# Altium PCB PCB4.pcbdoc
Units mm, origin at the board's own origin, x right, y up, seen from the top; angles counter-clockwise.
Board outline 46.06 x 44.7 mm, 2 copper layers (Top Layer, Bottom Layer); 67 components, 65 nets, 250 pads, 138 vias.
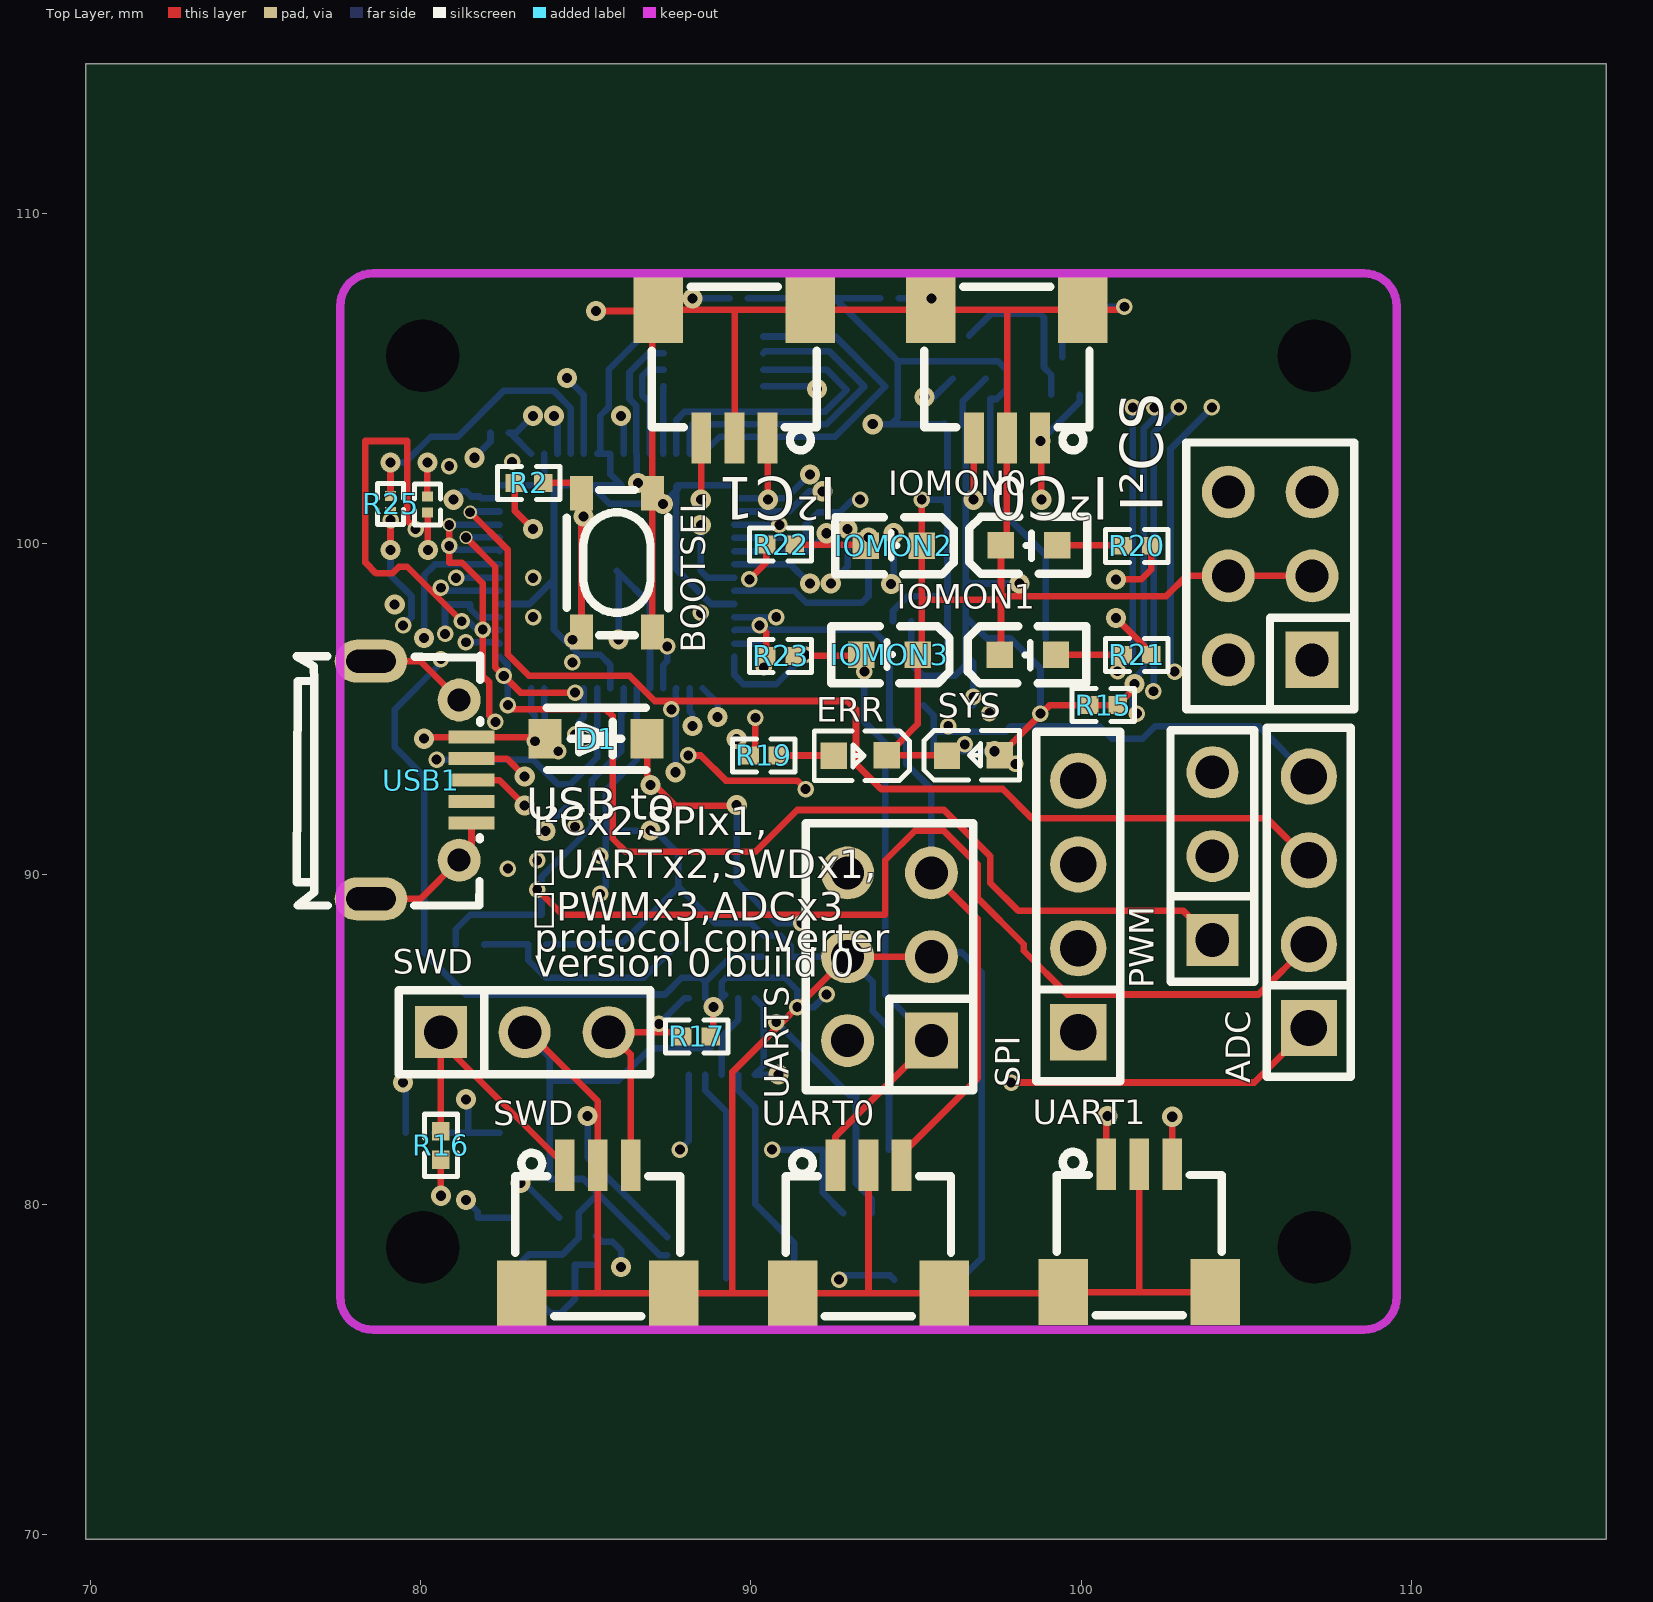
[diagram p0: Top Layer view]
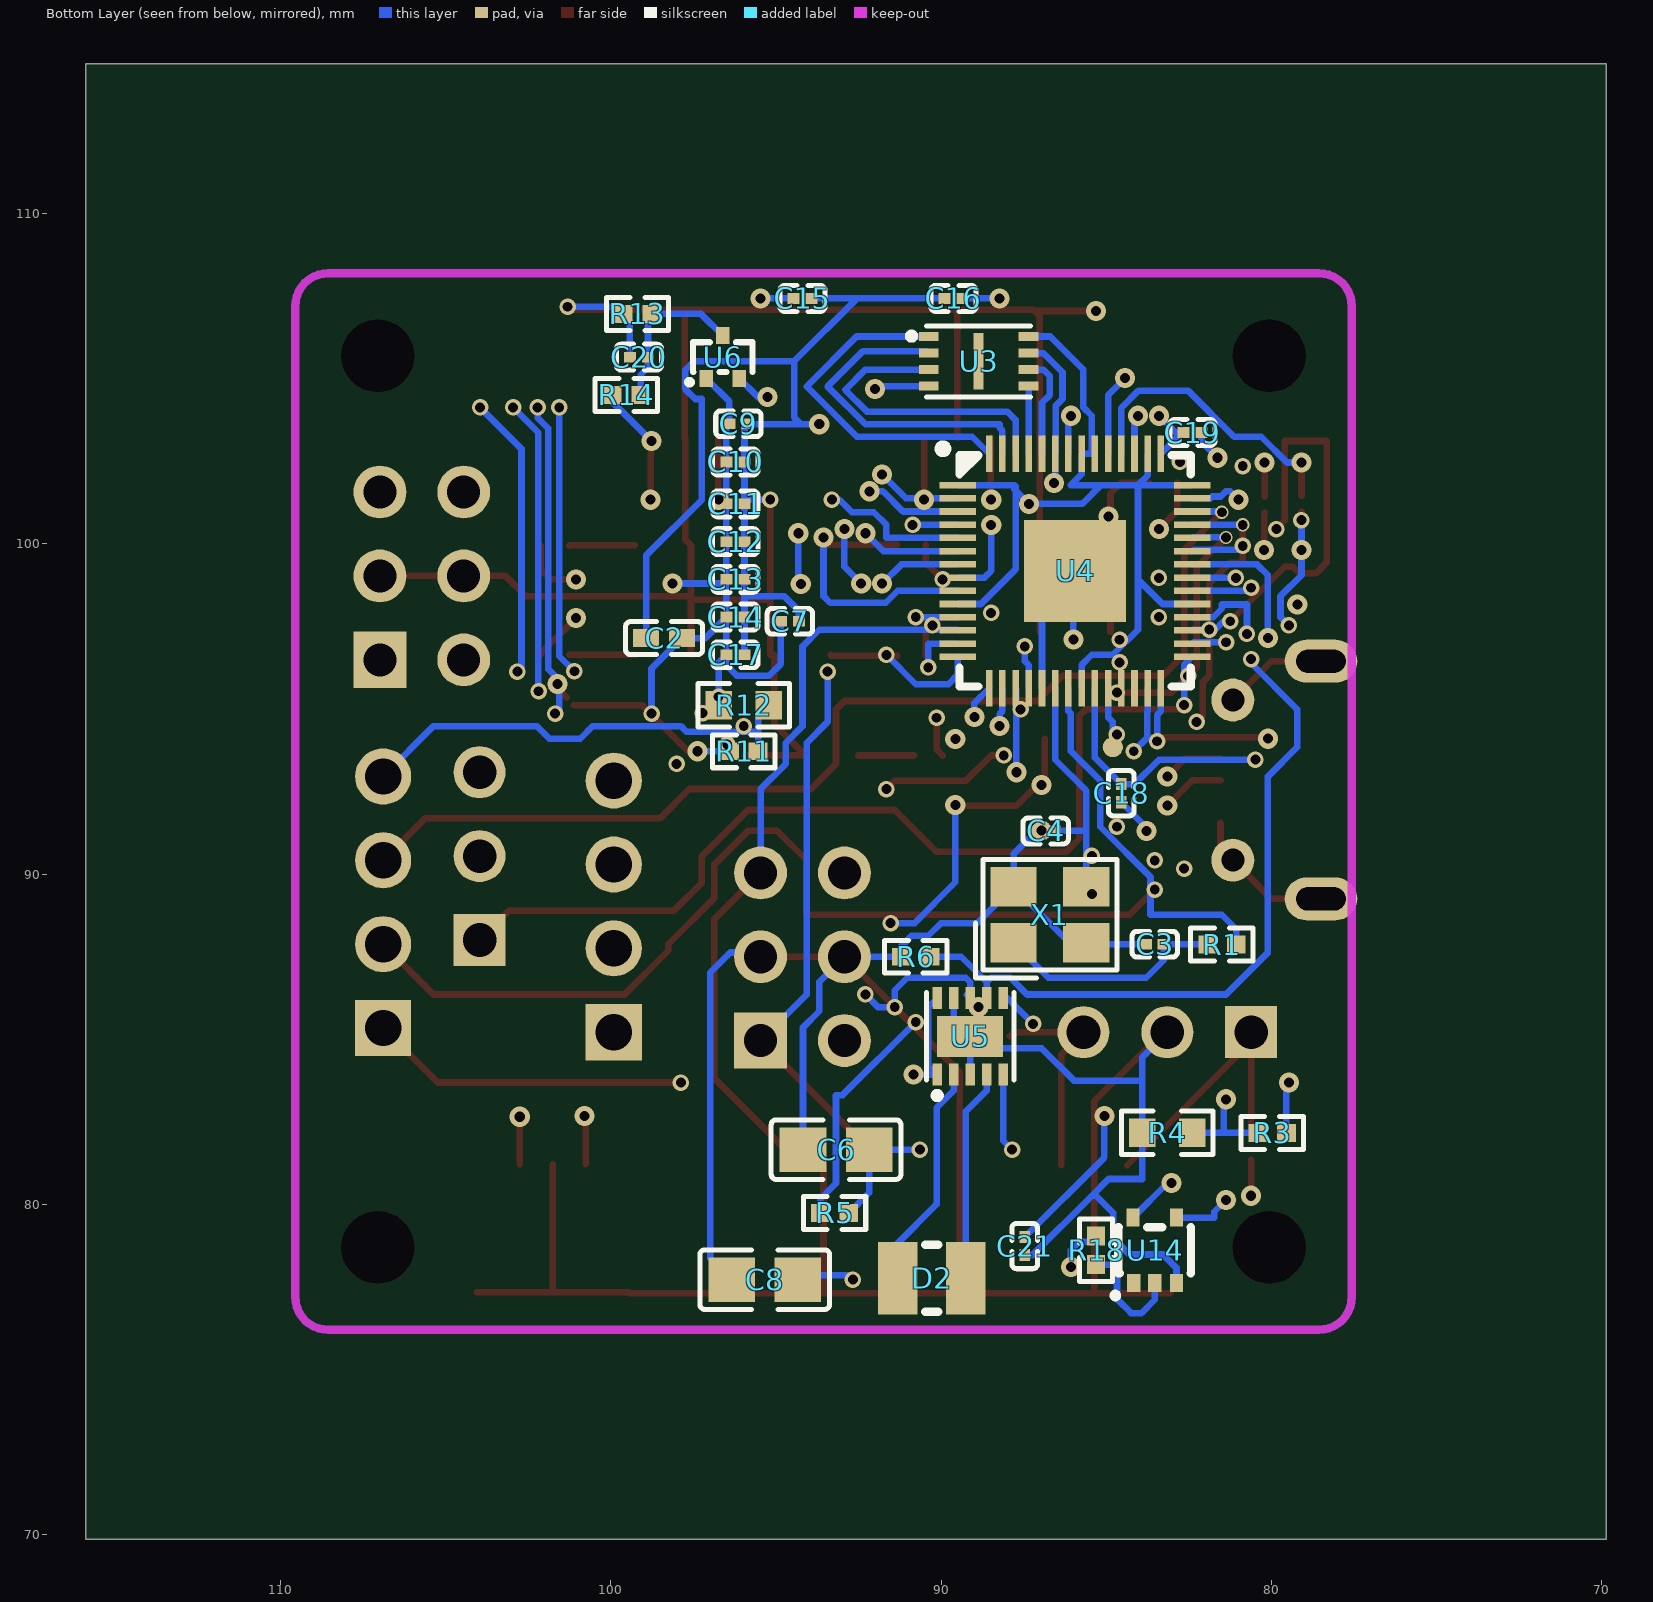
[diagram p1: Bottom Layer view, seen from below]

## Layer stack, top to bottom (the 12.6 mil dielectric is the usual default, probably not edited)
Top Layer: signal copper (thickness not stored)
Dielectric: dielectric 0.32, FR-4, Dk 4.8
Bottom Layer: signal copper (thickness not stored)

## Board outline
115.911,69.85 69.85,69.85 69.85,114.55 115.911,114.55
cut-out: 81.161,105.7 ccw(c80.061,105.7) 78.961,105.7 ccw(c80.061,105.7)
cut-out: 81.161,78.7 ccw(c80.061,78.7) 78.961,78.7 ccw(c80.061,78.7)
cut-out: 108.161,105.7 ccw(c107.061,105.7) 105.961,105.7 ccw(c107.061,105.7)
cut-out: 108.161,78.7 ccw(c107.061,78.7) 105.961,78.7 ccw(c107.061,78.7)

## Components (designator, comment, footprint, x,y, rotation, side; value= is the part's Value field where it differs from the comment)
ADC "2.54-1*4P母" HDR-TH_4P-P2.54-V-F 106.898,89.15 r90 top
BOOTSEL "SKRPACE010" KEY-SMD_4P-L4.2-W3.2-P2.20-LS4.6 85.943,99.437 r90 top
C2 "CL05A225MQ5NSNC" C0402 98.389,97.151 r0 bottom
C3 "CL03C150JA3ANNC" C0201 83.53,87.88 r180 bottom
C4 "CL03C150JA3ANNC" C0201 86.832,91.309 r180 bottom
C6 "GRM21BR60J476ME01L" C0805 93.182,81.657 r180 bottom
C7 "GRM033R60J104KE19D" C0201 94.579,97.659 r0 bottom
C8 "GRM21BR60J476ME01L" C0805 95.341,77.72 r0 bottom
C9 "GRM033R60J104KE19D" C0201 96.138,103.642 r180 bottom
C10 "GRM033R60J104KE19D" C0201 96.23,102.485 r180 bottom
C11 "GRM033R60J104KE19D" C0201 96.23,101.215 r180 bottom
C12 "GRM033R60J104KE19D" C0201 96.23,100.072 r180 bottom
C13 "GRM033R60J104KE19D" C0201 96.23,98.929 r180 bottom
C14 "GRM033R60J104KE19D" C0201 96.23,97.786 r180 bottom
C15 "GRM033R60J104KE19D" C0201 94.198,107.438 r0 bottom
C16 "GRM033R60J104KE19D" C0201 89.626,107.438 r0 bottom
C17 "GRM033R60J104KE19D" C0201 96.23,96.643 r0 bottom
C18 "GRM033R60J104KE19D" C0201 84.546,92.452 r90 bottom
C19 "GRM033R60J104KE19D" C0201 82.387,103.374 r0 bottom
C20 "GRM033R71E102KA01D" C0201 99.151,105.66 r180 bottom
C21 "GRM033R60J104KE19D" C0201 87.467,78.736 r270 bottom
D1 "MBR120VLSFT1G" SOD-123F_L2.8-W1.8-LS3.7-RD 85.308,94.103 r180 top
D2 "SRN2512-2R2M" IND-SMD_L2.5-W2.0 90.281,77.76 r180 bottom
ERR "NCD0603R1_C84263" LED0603-RD_RED 93.309,93.595 r180 top
IOMON0 "SZYY0603Y" LED0603-R-RD_YELLOW 98.425,99.96 r0 top
IOMON1 "SZYY0603Y" LED0603-R-RD_YELLOW 98.389,96.643 r0 top
IOMON2 "SZYY0603Y" LED0603-R-RD_YELLOW 94.325,99.945 r180 top
IOMON3 "SZYY0603Y" LED0603-R-RD_YELLOW 94.198,96.643 r180 top
I²C0 "SM03B-SRSS-TB(LF)(SN)" CONN-SMD_SM03B-SRSS-TB-LF-SN-P 97.754,105.152 r180 top
I²C1 "SM03B-SRSS-TB(LF)(SN)" CONN-SMD_SM03B-SRSS-TB-LF-SN-P 89.499,105.152 r180 top
I²CS "DS1023-2*3SF11" HDR-TH_6P-P2.54-V-F-R2-C3-S2.54 105.728,99.033 r90 top
PWM "2.54-1*3P母" HDR-TH_3P-P2.54-V-F 103.977,90.547 r90 top
R1 "AECR0402F1K00K9" R0402 81.496,87.868 r180 bottom
R2 "AECR0402F1K00K9" R0402 83.276,101.85 r0 top
R3 "CR0402F5K60Q10Z" R0402 79.974,82.165 r180 bottom
R4 "0603WAF1002T5E" R0603 83.149,82.165 r0 bottom
R5 "RC0402FR-07100KL" R0402 93.227,79.739 r180 bottom
R6 "RC0402FR-07100KL" R0402 90.769,87.499 r180 bottom
R11 "RC0402FR-071RL" R0402 95.976,93.722 r0 bottom
R12 "RC0603FR-07200RL" R0603 95.976,95.119 r180 bottom
R13 "RC0402FR-07100KL" R0402 99.196,106.968 r180 bottom
R14 "RC0402FR-07200KL" R0402 99.532,104.517 r0 bottom
R15 "RC0402FR-07470RL" R0402 100.675,95.119 r180 top
R16 "CR0402F100RQ10Z" R0402 80.609,81.784 r90 top
R17 "CR0402F100RQ10Z" R0402 88.356,85.086 r180 top
R18 "CR0402F100RQ10Z" R0402 85.308,78.609 r270 bottom
R19 "RC0402FR-07470RL" R0402 90.388,93.595 r0 top
R20 "RC0402FR-07470RL" R0402 101.691,99.945 r180 top
R21 "RC0402FR-07470RL" R0402 101.691,96.643 r180 top
R22 "RC0402FR-07470RL" R0402 90.897,99.982 r0 top
R23 "RC0402FR-07470RL" R0402 90.897,96.611 r0 top
R25 "RC0201FR-0727RL" R0201 79.085,101.215 r270 top
SPI "2.54-1*4P母" HDR-TH_4P-P2.54-V-F 99.913,89.023 r90 top
SWD "SM03B-SRSS-TB(LF)(SN)" CONN-SMD_SM03B-SRSS-TB-LF-SN-P 85.361,79.244 r0 top
SWD "2.54-1*3P母" HDR-TH_3P-P2.54-V-F 83.149,85.213 r0 top
SYS "19-217/GHC-YR1S2/3T" LED0603-RD 96.738,93.595 r0 top
U3 "W25Q16JVUXIQ" USON-8_L3.0-W2.0-P0.50-BL-EP 88.864,105.533 r270 bottom
U4 "RP2040_C2040" lqfn-56_l7.0-w7.0-p0.4-ep 85.943,99.183 r180 bottom
U5 "RT6150BGQW" WSON-10_L2.5-W2.5-P0.50-BL-EP 89.118,85.086 r180 bottom
U6 "DMG1012T-13" SOT-523-3_L1.6-W0.8-P1.00-LS1.6-BR 96.611,105.66 r270 bottom
U14 "74AUP1T17GWH" TSSOP-5_L2.1-W1.3-P0.65-LS2.2-BR 83.53,78.609 r270 bottom
UART0 "SM03B-SRSS-TB(LF)(SN)" CONN-SMD_SM03B-SRSS-TB-LF-SN-P 93.561,79.244 r0 top
UART1 "SM03B-SRSS-TB(LF)(SN)" CONN-SMD_SM03B-SRSS-TB-LF-SN-P 101.761,79.276 r0 top
UARTS "DS1023-2*3SF11" HDR-TH_6P-P2.54-V-F-R2-C3-S2.54 94.198,87.499 r90 top
USB1 "MicroXNJ" MICRO-USB-SMD_MICROXNJ 80.016,92.85 r270 top
X1 "X322512MMB4SI" CRYSTAL-SMD_4P-L3.2-W2.5-BL 86.705,88.769 r180 bottom
? "RC0201FR-0727RL" R0201 80.204,101.193 r270 top

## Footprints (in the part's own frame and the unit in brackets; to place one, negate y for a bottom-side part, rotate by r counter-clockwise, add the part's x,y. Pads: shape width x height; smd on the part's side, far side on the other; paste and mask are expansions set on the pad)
C0201 [mm]
  rect 0.368x0.324 smd paste-100 mask+0.051: 1(-0.274,0) 2(0.274,0)
  silkscreen extent -0.69,-0.39 0.69,0.39
C0402 [mm]
  rect 0.79x0.54 smd paste-100 mask+0.051: 1(-0.545,0) 2(0.545,0)
  silkscreen extent -1.17,-0.5 1.17,0.5
C0805 [mm]
  rect 1.41x1.35 smd paste-100 mask+0.051: 1(-1,0) 2(1,0)
  silkscreen extent -1.96,-0.9 1.96,0.9
CONN-SMD_SM03B-SRSS-TB-LF-SN-P [mm]
  rect 0.6x1.55 smd mask+0.051: 1(-1,1.938) 2(0,1.938) 3(1,1.938)
  rect 1.5x2 smd mask+0.051: 4(2.3,-1.938) 5(-2.3,-1.938)
  silkscreen extent -2.5,-2.64 2.5,2.32
CRYSTAL-SMD_4P-L3.2-W2.5-BL [mm]
  rect 1.4x1.2 smd paste+0 mask+0.051: 1(-1.1,-0.85) 2(1.1,-0.85) 3(1.1,0.85) 4(-1.1,0.85)
  silkscreen extent -2.26,-1.91 2.03,1.68
HDR-TH_3P-P2.54-V-F [mil]
  rect 62x62 hole 40.16 mask+2.01: 1(-100,0)
  round 62 hole 40.16 mask+2.01: 2(0,0) 3(100,0)
  silkscreen extent -150,-50 150,50
HDR-TH_4P-P2.54-V-F [mm]
  rect 1.7x1.7 hole 1.1 mask+0.051: 1(-3.81,0)
  round 1.7 hole 1.1 mask+0.051: 2(-1.27,0) 3(1.27,0) 4(3.81,0)
  silkscreen extent -5.29,-1.27 5.29,1.27
HDR-TH_6P-P2.54-V-F-R2-C3-S2.54 [mm]
  rect 1.7x1.6 hole 1 mask+0.051: 1(-2.54,-1.27)
  round 1.6 hole 1 mask+0.051: 2(-2.54,1.27) 3(0,-1.27) 4(0,1.27) 5(2.54,-1.27) 6(2.54,1.27)
  silkscreen extent -4.04,-2.54 4.04,2.54
IND-SMD_L2.5-W2.0 [mm]
  rect 1.2x2.2 smd paste+0 mask+0.051: 1(1.028,0) 2(-1.028,0)
  silkscreen extent -0.2,-1.02 0.2,1.02
KEY-SMD_4P-L4.2-W3.2-P2.20-LS4.6 [mm]
  rect 1.05x0.7 smd mask+0.051: 1(-2.1,1.075) 2(2.1,1.075) 3(-2.1,-1.075) 4(2.1,-1.075)
  silkscreen extent -2.2,-1.55 2.2,1.52
LED0603-R-RD_YELLOW [mm]
  rect 0.8x0.8 smd mask+0.051: 1(0.851,0) 2(-0.851,0)
  silkscreen extent -1.82,-0.86 1.77,0.86
LED0603-RD [mm]
  rect 0.8x0.8 smd paste+0 mask+0.051: 1(-0.799,-0.003) 2(0.799,0.003)
  silkscreen extent -1.49,-0.75 1.39,0.76
LED0603-RD_RED [mm]
  rect 0.8x0.8 smd mask+0.051: 1(-0.8,-0.003) 2(0.8,0.003)
  silkscreen extent -1.49,-0.75 1.39,0.76
lqfn-56_l7.0-w7.0-p0.4-ep [mm]
  rect 1.1x0.2 smd paste-100 mask+0.05: 1(-3.55,2.6) 2(-3.55,2.2) 3(-3.55,1.8) 4(-3.55,1.4) 5(-3.55,1) 6(-3.55,0.6) 7(-3.55,0.2) 8(-3.55,-0.2) 9(-3.55,-0.6) 10(-3.55,-1) 11(-3.55,-1.4) 12(-3.55,-1.8) 13(-3.55,-2.2) 14(-3.55,-2.6) 29(3.55,-2.6) 30(3.55,-2.2) 31(3.55,-1.8) 32(3.55,-1.4) 33(3.55,-1) 34(3.55,-0.6) 35(3.55,-0.2) 36(3.55,0.2) 37(3.55,0.6) 38(3.55,1) 39(3.55,1.4) 40(3.55,1.8) 41(3.55,2.2) 42(3.55,2.6)
  rect 0.2x1.1 smd paste-100 mask+0.05: 15(-2.6,-3.55) 16(-2.2,-3.55) 17(-1.8,-3.55) 18(-1.4,-3.55) 19(-1,-3.55) 20(-0.6,-3.55) 21(-0.2,-3.55) 22(0.2,-3.55) 23(0.6,-3.55) 24(1,-3.55) 25(1.4,-3.55) 26(1.8,-3.55) 27(2.2,-3.55) 28(2.6,-3.55) 43(2.6,3.55) 44(2.2,3.55) 45(1.8,3.55) 46(1.4,3.55) 47(1,3.55) 48(0.6,3.55) 49(0.2,3.55) 50(-0.2,3.55) 51(-0.6,3.55) 52(-1,3.55) 53(-1.4,3.55) 54(-1.8,3.55) 55(-2.2,3.55) 56(-2.6,3.55)
  rect 3.1x3.1 smd paste-100 mask+0.05: 57(0,0)
  silkscreen extent -4.13,-3.5 3.5,3.83
MICRO-USB-SMD_MICROXNJ [mm]
  rect 0.4x1.4 smd paste-100 mask+0.051: 1(-1.3,1.521) 2(-0.65,1.521) 3(0,1.521) 4(0.65,1.521) 5(1.3,1.521)
  round 1.3 hole 0.7 mask+0.051: 6(2.425,1.149) 9(-2.425,1.149)
  oval 1.3x2.2 hole 0.7 slot 1.5 at 90 deg mask+0.051: 7(3.6,-1.521) 8(-3.6,-1.521)
  silkscreen extent -3.76,-3.78 3.8,1.79
R0201 [mm]
  rect 0.303x0.324 smd paste-100 mask+0.051: 1(-0.242,0) 2(0.242,0)
  silkscreen extent -0.62,-0.39 0.62,0.39
R0402 [mm]
  rect 0.566x0.54 smd paste-100 mask+0.051: 1(-0.433,0) 2(0.433,0)
  silkscreen extent -0.94,-0.5 0.94,0.5
R0603 [mm]
  rect 0.806x0.864 smd paste-100 mask+0.051: 1(-0.753,0) 2(0.753,0)
  silkscreen extent -1.39,-0.66 1.39,0.66
SOD-123F_L2.8-W1.8-LS3.7-RD [mm]
  rect 1x1.2 smd paste+0 mask+0.051: 1(-1.55,0) 2(1.55,0)
  silkscreen extent -1.52,-0.93 1.49,0.95
SOT-523-3_L1.6-W0.8-P1.00-LS1.6-BR [mm]
  rect 0.51x0.4 smd paste+0 mask+0.051: 1(0.65,-0.5) 2(0.65,0.5) 3(-0.65,0)
  silkscreen extent -0.45,-1.08 0.83,0.9
TSSOP-5_L2.1-W1.3-P0.65-LS2.2-BR [mil]
  rect 21.7x15.7 smd paste+0 mask+1.97: 1(39,-25) 2(39,0) 3(39,26) 4(-39,26) 5(-39,-26)
  silkscreen extent -28,-49 56,43
USON-8_L3.0-W2.0-P0.50-BL-EP [mm]
  rect 0.28x0.6 smd paste+0 mask+0.051: 1(-0.75,-1.507) 2(-0.25,-1.507) 3(0.25,-1.507) 4(0.75,-1.507) 5(0.75,1.507) 6(0.25,1.507) 7(-0.25,1.507) 8(-0.75,1.507)
  rect 1.7x0.3 smd paste+0 mask+0.051: 9(0,0)
  silkscreen extent -1.08,-2.13 1.08,1.58
WSON-10_L2.5-W2.5-P0.50-BL-EP [mm]
  rect 0.28x0.665 smd paste+0 mask+0.051: 1(-1,-1.157) 2(-0.5,-1.157) 3(0,-1.157) 4(0.5,-1.157) 5(1,-1.157) 6(1,1.157) 7(0.5,1.157) 8(0,1.157) 9(-0.5,1.157) 10(-1,1.157)
  rect 2x1.25 smd paste+0 mask+0.051: 11(0,0)
  silkscreen extent -1.33,-1.89 1.33,1.33

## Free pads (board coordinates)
  round 0.61 smd far side mask+0.051: TP1(84.8,93.849)

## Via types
v1: diameter 0.5, hole 0.3, Top Layer to Bottom Layer, 68 vias
v2: diameter 0.61, hole 0.305, Top Layer to Bottom Layer, 65 vias
v3: diameter 0.4, hole 0.3, Top Layer to Bottom Layer, 3 vias
v4: diameter 0.5, hole 0.305, Top Layer to Bottom Layer, 2 vias

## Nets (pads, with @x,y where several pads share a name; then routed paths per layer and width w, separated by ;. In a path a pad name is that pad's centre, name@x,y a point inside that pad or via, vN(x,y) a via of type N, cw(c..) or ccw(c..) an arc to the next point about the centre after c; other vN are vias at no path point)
0ADC0: ADC.1 U4.38 | length 41.9
  Top Layer w0.2: v3(81.371,100.199) 82.26,99.31 82.26,96.262 83.022,95.5 v1(84.673,95.5) ; v1(97.881,83.689) 105.247,83.689 ADC.1
  Inner1 w0.2: v1(84.673,91.436) v1(84.673,94.23) ; v1(85.435,89.404) v1(85.435,90.551)
  Inner2 w0.2: v1(84.673,91.436) 84.673,91.313 v1(85.435,90.551) ; v1(84.673,94.23) v1(84.673,95.5) ; v1(85.435,89.404) 91.531,89.404 92.293,88.642 94.198,88.642 94.198,83.689 v1(97.881,83.689)
  Bottom Layer w0.2: v3(81.371,100.199) 82.377,100.199 U4.38
0ADC1: ADC.2 U4.39 | length 43.8
  Top Layer w0.2: v3(80.863,100.58) 80.863,99.437 81.244,99.437 81.879,98.802 81.879,96.008 82.079,95.808 82.079,94.792 v1(82.26,94.611) ; v1(83.53,89.531) 84.292,88.769 94.071,88.769 94.071,90.42 94.96,91.309 95.849,91.309 96.865,90.293 96.865,89.277 98.262,87.88 98.262,87.68 99.586,86.356 105.374,86.356 ADC.2
  Inner1 w0.2: v1(82.26,94.611) 82.105,94.455 82.105,89.814 82.387,89.531 v1(83.53,89.531)
  Bottom Layer w0.2: v3(80.863,100.58) 82.39,100.58 U4.39
0ADC2: ADC.3 U4.40 | length 33.5
  Top Layer w0.2: v3(81.498,100.961) 82.641,99.818 82.641,96.643 83.276,96.008 86.324,96.008 87.086,95.246 92.928,95.246 93.182,94.992 93.182,93.341 93.944,92.579 97.627,92.579 98.516,91.69 105.628,91.69 ADC.3
  Bottom Layer w0.2: v3(81.498,100.961) 81.52,100.983 U4.40
0CPU-U: R15.1 U4.37 | length 32.9
  Top Layer w0.2: v1(88.102,93.595) 88.483,93.595 89.245,92.833 91.404,92.833 v1(91.658,92.579) ; R15.1@101.333,95.344 101.619,95.63 v2(101.619,95.754)
  Inner1 w0.2: v1(80.863,99.945) 80.863,99.691 84.165,96.389 84.165,95.26 84.433,94.992 v1(87.594,94.992) ; v1(96.476,93.93) 97.221,94.675 v1(97.221,94.88)
  Inner2 w0.2: v1(87.594,94.992) 87.594,94.103 v1(88.102,93.595) ; v1(91.658,92.579) 91.658,94.611 92.166,95.119 94.706,95.119 95.468,94.357 95.468,94.087 95.707,93.849 96.395,93.849 v1(96.476,93.93) ; v1(97.221,94.88) 97.642,94.88 99.786,97.024 101.564,97.024 101.691,96.897 101.691,95.826 v2(101.619,95.754)
  Bottom Layer w0.2: v1(80.863,99.945) 80.977,99.831 82.345,99.831 U4.37
0GP10: R19.1 U4.13 | length 4.5
  Top Layer w0.2: R19.1 90.134,93.774 v1(90.134,94.738)
  Inner1 w0.2: v1(90.134,94.738) 90.388,94.992 v1(90.388,96.262)
  Bottom Layer w0.2: U4.13 90.388,96.983 v1(90.388,96.262)
0GP11: R20.1 U4.14 | length 22.8
  Top Layer w0.2: v2(101.056,98.929) 101.823,98.929 102.124,99.23 R20.1
  Inner1 w0.2: v1(88.483,97.913) 88.61,98.04 89.245,98.04 89.245,99.056 89.626,99.437 100.548,99.437 v2(101.056,98.929)
  Inner2 w0.2: v1(88.483,97.913) 89.753,96.643 v1(91.658,96.643)
  Bottom Layer w0.2: U4.14 89.499,96.577 89.499,96.031 89.777,95.754 90.769,95.754 v1(91.658,96.643)
0GP15: R21.1 U4.18 | length 18.9
  Top Layer w0.2: v2(101.056,97.762) 102.124,96.695 R21.1
  Inner1 w0.2: v1(95.976,94.484) 96.738,95.246 v1(96.738,95.373)
  Inner2 w0.2: v1(87.467,96.897) 88.437,96.897 89.882,95.452 95.008,95.452 v1(95.976,94.484) ; v1(96.738,95.373) 99.024,97.659 100.953,97.659 v2(101.056,97.762)
  Bottom Layer w0.2: U4.18 87.343,96.333 87.467,96.457 v1(87.467,96.897)
0GP19: R22.1 U4.30 | length 12.5
  Top Layer w0.2: v1(89.953,98.925) 90.464,99.436 R22.1
  Inner1 w0.2: v1(84.593,97.098) 84.774,97.098 85.308,96.564 88.277,96.564 89.953,98.239 v1(89.953,98.925)
  Inner2 w0.2: v1(81.371,97.024) 84.519,97.024 v1(84.593,97.098)
  Bottom Layer w0.2: v1(81.371,97.024) 82.352,97.024 U4.30
0GP21: R23.1 U4.32 | length 14.4
  Top Layer w0.2: v1(90.261,97.532) 90.464,97.329 R23.1
  Inner1 w0.2: v1(84.593,96.414) 84.745,96.262 88.991,96.262 v1(90.261,97.532)
  Inner2 w0.2: v1(80.736,97.278) 80.736,97.049 81.161,96.624 84.383,96.624 v1(84.593,96.414)
  Bottom Layer w0.2: v1(80.736,97.278) 80.736,98.167 81.498,98.167 81.498,98.04 81.755,97.783 U4.32
0GPIO23: R6.2 U4.35 U5.7 | length 32.1
  Inner1 w0.2: v1(81.879,97.405) 82.514,96.77 v4(82.514,96.008) ; v1(83.403,97.786) v1(83.403,98.972)
  Inner2 w0.2: v1(80.609,96.516) 80.609,96.262 82.26,96.262 v4(82.514,96.008) ; v1(81.075,98.972) v1(83.403,98.972) ; v1(81.879,97.405) 83.022,97.405 v1(83.403,97.786)
  Bottom Layer w0.2: v1(80.609,96.516) 80.609,96.389 79.212,94.992 79.212,93.849 80.101,92.96 80.101,87.626 81.371,86.356 87.394,86.356 87.902,86.864 88.481,86.864 88.618,86.727 ; v1(81.075,98.972) 82.382,98.972 U4.35 ; U5.7 88.618,86.727 ; R6.2 89.39,87.499 88.618,86.727
0GPIO24: R3.1 R4.1 U4.36 | length 22.6
  Inner2 w0.2: v2(80.101,97.151) 80.101,94.992 82.26,92.833 82.26,89.277 81.776,88.793 81.776,83.586 v2(81.371,83.181)
  Bottom Layer w0.2: v2(80.101,97.151) 80.101,99.056 80.428,99.383 U4.36 ; R3.1 81.434,82.165 ; v2(81.371,83.181) 81.434,83.118 81.434,82.165 ; R4.1 81.434,82.165
0USB0: ?.1 U4.47 | length 8.8
  Top Layer w0.2: ?.1 80.204,102.461 v2(80.21,102.468)
  Inner2 w0.2: v2(80.21,102.468) 82.768,105.025 v2(84.425,105.025)
  Bottom Layer w0.2: v2(84.425,105.025) 84.943,104.507 U4.47
0USB1: R25.1 U4.46 | length 9
  Top Layer w0.2: R25.1 v2(79.085,102.468)
  Bottom Layer w0.2: v2(79.085,102.468) 79.526,102.468 80.305,103.247 81.125,103.247 82.522,104.644 84.019,104.644 84.546,104.117 84.546,102.736 U4.46
1V10: C15.2 C16.1 C18.2 U4.23 U4.45 U4.50 | length 45.6
  Inner1 w0.2: v1(79.085,100.723) 79.229,100.723 v1(80.863,102.358) ; v1(79.466,97.532) 80.101,96.897 80.101,94.865 80.863,94.103 80.863,93.849 v1(80.482,93.468)
  Inner2 w0.2: v1(80.863,102.358) 80.863,102.612 81.371,103.12 81.498,103.12 81.752,103.374 82.133,103.374 82.768,104.009 82.768,104.39 84.165,104.39 84.673,103.882 ; v2(84.038,103.882) 84.673,103.882 ; v2(86.07,103.882) 86.07,104.136 88.275,106.341 ; v2(88.229,107.438) 87.704,106.913 ; v2(95.468,107.438) 89.372,107.438 88.275,106.341 ; 84.673,103.882 87.704,106.913 ; 87.704,106.913 88.275,106.341
  Bottom Layer w0.2: v1(79.085,100.723) 79.085,99.056 79.72,98.421 79.72,97.786 v1(79.466,97.532) ; v1(80.482,93.468) 83.403,93.468 84.145,92.726 C18.2 85.343,93.523 U4.23 ; v2(84.038,103.882) 84.143,103.777 U4.45 ; v2(86.07,103.882) 86.143,103.809 U4.50 ; v2(88.229,107.438) C16.1 ; C15.2 v2(95.468,107.438)
12: R16.1 U4.15 | length 21.3
  Top Layer w0.2: v2(80.609,80.26) R16.1
  Inner1 w0.2: v2(80.609,80.26) 84.292,83.943 84.292,90.293 85.943,91.944 87.975,91.944 88.61,92.579 88.61,94.23 88.704,94.324 88.704,94.471 v2(88.991,94.758)
  Bottom Layer w0.2: U4.15 88.991,95.185 v2(88.991,94.758)
13: U4.16 U14.4 | length 20.5
  Inner1 w0.2: v2(81.371,80.133) 81.879,80.641 82.387,80.641 84.594,82.848 84.594,86.15 86.959,88.515 v2(86.959,91.319) ; v2(86.959,92.706) 86.959,93.214 v2(88.229,94.484)
  Inner2 w0.2: v2(86.959,91.319) v2(86.959,92.706)
  Bottom Layer w0.2: v2(81.371,80.133) 81.727,79.777 81.727,79.6 U14.4 ; U4.16 88.143,94.933 88.229,94.847 v2(88.229,94.484)
14: R17.1 U4.17 | length 14.5
  Top Layer w0.2: R17.1 88.864,85.161 v2(88.864,85.975)
  Inner1 w0.2: v2(88.864,85.975) 88.991,86.102 88.991,93.722 89.363,94.094 v2(89.57,94.094)
  Inner2 w0.2: v2(87.721,93.087) 87.975,92.833 88.102,92.833 89.363,94.094 v2(89.57,94.094)
  Bottom Layer w0.2: v2(87.721,93.087) 87.721,95.611 U4.17
$1N2647: R5.1 U5.6 | length 11.9
  Inner2 w0.2: v1(87.213,85.467) 90.715,85.467 v1(90.769,85.521)
  Bottom Layer w0.2: v1(87.213,85.467) 87.99,86.243 U5.6 ; v1(90.769,85.521) 92.982,83.308 93.182,83.308 93.182,80.637 93.659,80.16 R5.1
$1N2652: D2.1 U5.4 | length 6.4
  Bottom Layer w0.2: U5.4 88.618,83.445 89.253,82.811 D2.1
$1N2653: D2.2 U5.2 | length 6.9
  Bottom Layer w0.2: U5.2 89.618,83.445 90.134,82.929 90.134,80.006 91.309,78.831 D2.2
$1N2691: C3.2 R1.1 X1.1 | length 7
  Bottom Layer w0.2: R1.1 81.941,87.88 C3.2 83.256,87.392 83.784,86.864 86.75,86.864 X1.1
$1N2815: U4.41 U6.2 | length 18.7
  Inner2 w0.2: v2(80.99,101.342) 86.832,101.342 87.467,101.977 90.769,101.977 91.404,102.612 93.563,102.612 93.944,102.993 94.579,102.993 94.579,103.773 v2(95.254,104.448)
  Bottom Layer w0.2: v2(80.99,101.342) 81.244,101.596 81.371,101.596 81.529,101.438 81.783,101.438 81.838,101.383 U4.41 ; v2(95.254,104.448) 95.549,104.448 U6.2
$1N2838: C20.2 R13.2 R14.1 U6.3 | length 5
  Bottom Layer w0.2: U6.3 97.269,106.968 R13.2 98.877,106.855 C20.2 98.877,105.347 99.099,105.125 R14.1
$1N4030: BOOTSEL.1 BOOTSEL.2 R2.2 | length 5.5
  Top Layer w0.2: R2.2 84.555,101.85 BOOTSEL.2 BOOTSEL.1
$1N4773: R18.2 U14.2 | length 3.7
  Bottom Layer w0.2: U14.2 83.53,77.109 83.935,76.704 84.258,76.704 84.258,76.723 84.673,77.137 84.673,78.176 R18.2
$1N4884: R15.2 SYS.2 | length 4.2
  Top Layer w0.2: SYS.2 99.058,95.119 R15.2 101.131,95.119
$1N5172: ERR.2 R19.2 | length 1.7
  Top Layer w0.2: R19.2 92.506,93.595 ERR.2
$1N5459: IOMON0.1 R20.2 | length 2
  Top Layer w0.2: IOMON0.1 101.244,99.96 R20.2
$1N5495: IOMON1.1 R21.2 | length 2
  Top Layer w0.2: IOMON1.1 R21.2@101.258,96.643
$1N5531: IOMON2.1 R22.2 | length 2.2
  Top Layer w0.2: R22.2 93.438,99.982 IOMON2.1
$1N5567: IOMON3.1 R23.2 | length 2
  Top Layer w0.2: R23.2 93.315,96.611 IOMON3.1
$1N5599: C19.2 R11.2 U4.43 | length 21.9
  Inner1 w0.2: v2(83.403,103.882) 83.403,102.358 v2(84.927,100.834)
  Inner2 w0.2: v2(84.927,100.834) 90.007,95.754 95.341,95.754 v2(97.373,93.722)
  Bottom Layer w0.2: C19.2 C19.2@82.702,103.374 ; U4.43 C19.2@82.702,103.374 ; v2(83.403,103.882) 82.895,103.374 C19.2@82.702,103.374 ; R11.2 v2(97.373,93.722)
$1N5775: R25.2 USB1.2 | length 12
  Top Layer w0.2: v2(79.085,99.818) R25.2 ; USB1.2 82.609,93.5 v2(83.149,92.96)
  Inner1 w0.2: v2(79.085,99.818) 79.085,99.691 79.974,98.802 79.974,97.913 82.387,95.5 83.149,95.5 v2(83.149,92.96)
$1N5777: ?.2 USB1.3 | length 12.6
  Top Layer w0.2: ?.2 80.219,100.936 v2(80.219,99.818) ; USB1.3 82.379,92.85 v2(83.149,92.08)
  Inner1 w0.2: v2(80.219,99.818) 80.228,99.818 81.208,98.839 83.784,96.262 83.784,92.715 v2(83.149,92.08)
$1N5998: C6.2 D1.1 R5.2 R14.2 U5.5 U5.8 | length 48.4
  Top Layer w0.2: D1.1 86.858,92.934 87.721,92.071 89.541,92.071 v2(89.57,92.1)
  Inner1 w0.2: v2(89.57,92.1) 91.023,93.553 91.023,97.424 92.401,98.802 v2(92.42,98.802) ; v2(92.928,100.453) 94.96,102.485 98.135,102.485 v2(98.77,103.12)
  Inner2 w0.2: v1(87.848,81.657) v1(90.642,81.657) 90.642,82.551 90.648,82.551 91.404,83.308 v1(91.404,85.975) ; v1(91.531,88.515) 91.531,87.118 v1(92.293,86.356)
  Bottom Layer w0.2: v1(87.848,81.657) 88.118,81.927 U5.5 ; U5.8@89.226,86.351 U5.8 89.118,86.727 89.255,86.864 91.023,86.864 91.404,86.483 v1(91.404,85.975) 91.912,85.975 v1(92.293,86.356) ; v2(89.57,92.1) 89.57,89.753 90.808,88.515 v1(91.531,88.515) ; v1(90.642,81.657) C6.2 92.182,80.35 R5.2 ; v2(92.42,98.802) 92.928,99.31 v2(92.928,100.453) ; v2(98.77,103.12) 99.965,104.315 R14.2
ADC_VERF: ADC.4 R11.1 R12.2 | length 13.9
  Bottom Layer w0.2: R12.2 95.543,94.798 95.543,94.314 ; R11.1 95.543,94.314 ; ADC.4 105.374,94.484 102.244,94.484 101.863,94.103 100.929,94.103 100.548,94.484 97.881,94.484 97.712,94.314 95.543,94.314
AVCC: D1.2 R3.2 USB1.1 | length 15.9
  Top Layer w0.2: v2(80.101,94.103) 80.148,94.15 USB1.1 83.711,94.15 D1.2
  Inner2 w0.2: v2(79.466,83.689) 79.466,86.737 80.101,87.372 v2(80.101,94.103)
  Bottom Layer w0.2: v2(79.466,83.689) 79.541,83.614 R3.2
BOOTSEL_TO_EEPROM: R2.1 U3.7 U4.51 | length 11.3
  Top Layer w0.2: R2.1 82.843,101.013 v2(83.403,100.453)
  Inner1 w0.2: v2(83.403,100.453) 83.657,100.199 86.578,100.199 v2(86.578,101.85)
  Bottom Layer w0.2: v2(86.578,101.85) 86.543,101.885 U4.51 86.524,102.752 86.524,104.19 86.324,104.39 86.324,105.201 86.906,105.783 U3.7
EPCLK0: U3.6 U4.52 | length 3.2
  Bottom Layer w0.2: U4.52 86.943,104.279 86.705,104.517 86.705,105.082 86.906,105.283 U3.6
EPSD00: U3.5 U4.53 | length 2.1
  Bottom Layer w0.2: U4.53 87.343,104.769 U3.5
EPSD10: U3.2 U4.55 | length 10.1
  Bottom Layer w0.2: U4.55 88.143,103.433 88.229,103.519 88.229,103.628 92.293,103.628 93.436,104.771 92.364,105.843 90.432,105.843 U3.2
EPSD20: U3.3 U4.54 | length 9.3
  Bottom Layer w0.2: U4.54 87.743,103.755 87.997,104.009 92.247,104.009 92.905,104.667 92.289,105.283 U3.3
EPSS0: U3.1 U4.56 | length 10.7
  Bottom Layer w0.2: U4.56 89.057,103.247 92.547,103.247 94.071,104.771 92.559,106.283 U3.1
GND: BOOTSEL.3 BOOTSEL.4 C2.2 C3.1 C4.1 C6.1 C7.1 C8.2 C9.2 C10.2 C11.2 C12.2 C13.2 C14.2 C15.1 C16.2 C17.1 C18.1 C19.1 C20.1 C21.2 ERR.1 IOMON0.2 IOMON1.2 IOMON2.2 IOMON3.2 I²C0.2 I²C0.4 I²C0.5 I²C1.2 I²C1.4 I²C1.5 I²CS.3 I²CS.4 R4.2 R6.1 R13.1 SWD.2 SWD.4 SWD.5 SYS.1 U3.4 U4.19 U4.57 U5.3 U5.9 U5.11 U14.3 UART0.2 UART0.4 UART0.5 UART1.2 UART1.4 UART1.5 UARTS.3 UARTS.4 USB1.5 USB1.6 USB1.7 USB1.8 USB1.9 X1.2 X1.4 | length 265.9
  Top Layer w0.2: USB1.7 79.99,89.25 USB1.6 81.538,90.798 USB1.5 ; USB1.8 79.99,96.45 USB1.9 ; SWD.5 85.334,77.306 ; SWD.2@83.149,85.213 83.276,85.213 85.361,83.128 85.361,81.182 85.361,77.334 85.334,77.306 ; v2(85.308,107.057) I²C1.4@87.167,107.057 ; BOOTSEL.3 BOOTSEL.4 87.018,106.909 I²C1.4@87.167,107.057 ; I²C1.2 89.512,103.228 89.512,107.09 ; 93.561,77.307 UART0.2 ; v1(95.176,101.342) IOMON2.2 95.176,98.311 ; UARTS.3 UARTS.4 89.439,84.009 89.439,77.306 ; SYS.1 95.932,93.598 ERR.1 95.049,94.539 IOMON3.2 95.17,96.643 95.176,96.649 95.176,98.311 ; IOMON1.2 97.574,96.678 97.574,98.271 ; v1(101.31,107.184) 101.216,107.09 I²C0.5 97.759,107.09 ; UART1.2 101.761,77.346 101.754,77.338 ; UART1.4 101.754,77.338 ; I²CS.3 I²CS.4 103.192,99.033 102.58,98.421 97.593,98.421 97.574,98.402 ; 85.334,77.306 SWD.4 89.439,77.306 ; I²C1.4@87.167,107.057 I²C1.4 89.512,107.09 ; 89.439,77.306 UART0.5 UART0.4 99.429,77.306 UART1.5 101.754,77.338 ; 89.512,107.09 I²C1.5 I²C0.4 97.759,107.09 ; 95.176,98.311 97.533,98.311 97.574,98.271 ; 97.574,98.271 97.574,98.402 ; 97.574,98.402 IOMON0.2 97.754,100.14 I²C0.2 97.759,103.22 97.759,107.09
  Inner1 w0.2: USB1.7 USB1.8 78.495,98.167 ; v2(79.212,98.167) 78.495,98.167 ; USB1.6 81.165,87.197 SWD.2@83.149,85.213 ; v2(81.625,102.612) 81.371,102.866 80.609,102.866 ; v2(85.308,107.057) 84.8,107.057 80.609,102.866 ; 78.495,98.167 78.495,101.234 80.127,102.866 80.609,102.866
  Inner2 w0.2: v2(79.212,98.167) 84.165,98.167 85.181,97.151 ; v2(83.784,91.309) 83.784,91.436 84.546,92.198 84.546,92.706 85.308,93.468 85.308,97.024 85.181,97.151 ; v2(85.995,97.108) 85.952,97.151 85.181,97.151 ; v2(91.999,104.699) 93.07,103.628 v2(93.69,103.628)
  Bottom Layer w0.2: v2(81.625,102.612) 82.113,103.1 C19.1 ; U14.3 82.87,78.076 83.276,78.482 84.292,78.482 84.786,78.976 84.786,79.738 85.31,80.261 85.434,80.261 ; SWD.2@83.149,85.213 83.903,84.46 83.903,83.747 ; v2(83.784,91.309) 83.784,91.416 C18.1 ; C3.1 85.566,87.88 X1.2 86.105,87.919 X1.4 ; U4.57 U4.57@85.995,99.131 ; v2(85.995,97.108) U4.57@85.995,99.131 ; U4.19 86.943,98.183 U4.57@85.995,99.131 ; C4.1 87.805,90.61 X1.4 ; C21.2 87.234,78.462 85.434,80.261 ; U5.3 U5.11 ; U5.9 89.618,85.586 U5.11 ; C16.2 92.547,107.438 ; U3.4 91.915,104.783 v2(91.999,104.699) ; v2(93.69,103.628) 94.246,103.628 ; C15.1 92.547,107.438 ; C6.1 94.182,85.356 93.69,85.848 93.69,86.737 UARTS.4 R6.1 91.202,87.828 90.896,88.134 90.388,88.134 90.007,88.515 88.909,88.515 X1.4 ; C7.1 94.305,97.972 94.754,98.421 95.933,98.421 95.956,98.444 ; v1(95.176,101.342) 95.829,101.342 C11.2 ; UARTS.3 95.595,87.626 96.386,87.626 96.992,87.02 96.992,78.371 C8.2 ; C17.1 C14.2 95.956,98.444 ; C2.2 98.934,99.654 97.246,101.342 97.246,104.39 97.446,104.39 97.754,104.698 97.754,105.26 97.482,105.533 94.452,105.533 ; C20.1 99.426,106.764 R13.1 99.845,107.184 v1(101.31,107.184) ; 83.903,83.747 85.979,83.747 86.959,84.727 88.76,84.727 U5.11 ; 83.903,83.747 R4.2 83.903,80.766 83.905,80.768 84.927,80.768 85.434,80.261 ; 92.547,107.438 94.452,105.533 ; 94.246,103.628 94.452,103.834 94.452,105.533 ; 94.246,103.628 95.85,103.628 C9.2 95.956,103.549 C10.2 C11.2 ; 95.956,98.444 C13.2 C12.2 C11.2
I0C: I²C0.1 I²CS.1 U4.7 | length 32.3
  Top Layer w0.2: I²C0.1 98.798,103.171 v2(98.798,101.342)
  Inner1 w0.2: v2(98.798,101.342) 98.897,101.342 100.929,103.374 108.041,103.374 109.057,102.358 109.057,98.552 I²CS.1
  Inner2 w0.2: v2(91.785,98.802) 91.785,98.397 92.015,98.167 93.626,98.167 v2(94.249,98.79) ; v2(94.325,100.326) 97.782,100.326 v2(98.798,101.342)
  Bottom Layer w0.2: U4.7 91.204,99.383 v2(91.785,98.802) ; v2(94.249,98.79) 94.325,98.866 v2(94.325,100.326)
I0D: I²C0.3 I²CS.5 U4.6 | length 23.2
  Top Layer w0.2: v2(96.738,101.342) 96.754,101.358 I²C0.3
  Inner1 w0.2: v2(96.738,101.342) 97.5,100.58 101.31,100.58 103.596,102.866 105.705,102.866 I²CS.5
  Inner2 w0.2: v2(92.293,100.326) 92.293,100.731 92.674,101.112 92.674,101.596 92.801,101.723 94,101.723 95.016,100.707 96.103,100.707 v2(96.738,101.342)
  Bottom Layer w0.2: U4.6 91.75,99.783 v2(92.293,100.326)
I1C: I²C1.1 I²CS.2 U4.9 | length 24.3
  Top Layer w0.2: I²C1.1 90.515,103.199 v2(90.515,101.342)
  Inner2 w0.2: v2(90.515,101.342) 90.642,101.342 92.166,99.818 93.502,99.818 ; v2@93.502,100.199 93.502,99.818 ; I²CS.2 101.133,99.818 93.502,99.818
  Bottom Layer w0.2: U4.9 91.312,98.583 91.674,98.221 93.363,98.221 93.563,98.421 v2(93.563,100.199)
I1D: I²C1.3 I²CS.6 U4.8 | length 22.5
  Top Layer w0.2: v2(88.483,101.342) 88.499,101.358 I²C1.3
  Inner1 w0.2: v2(88.483,100.58) v2(88.483,101.342) 90.007,99.818 90.85,99.818 102.703,99.818 I²CS.6
  Bottom Layer w0.2: v2(88.483,100.58) 88.483,99.185 88.685,98.983 U4.8
IOVDD00: C2.1 C7.2 C8.1 C9.1 C10.1 C11.1 C12.1 C13.1 C14.1 C17.2 C21.1 R12.1 U3.8 U4.1 U4.10 U4.22 U4.33 U4.42 U4.44 U4.48 U4.49 U5.1 U5.10 U6.1 U14.5 | length 114.4
  Inner2 w0.2: v2(83.022,80.641) v2(85.054,82.673) 85.452,83.07 ; v2(87.34,101.215) 89.626,101.215 91.531,99.31 97.627,99.31 v2(98.135,98.802) ; v2(90.838,83.929) 90.725,83.816 86.197,83.816 85.452,83.07 ; v1(98.77,94.865) 98.77,94.453 98.008,93.691 v1(98.008,93.341) 98.008,85.213 98.516,84.705 98.516,80.133 97.754,79.371 94.452,79.371 93.817,78.736 93.69,78.736 v1(92.674,77.72) 89.118,77.72 89.118,79.404 85.452,83.07
  Bottom Layer w0.2: U4.33 83.292,98.183 84.038,98.929 ; U4.42 84.038,101.783 ; v2(83.022,80.641) 83.149,80.641 U14.5 ; U4.44 83.743,102.078 84.038,101.783 ; v2(85.054,82.673) 85.054,81.423 C21.1 ; U4.22 85.743,96.333 85.435,96.643 84.8,96.643 84.038,97.405 84.038,98.929 ; U3.8 86.693,106.283 85.689,105.279 85.689,104.136 85.435,103.882 85.435,102.825 U4.48 U4.49 85.743,102.11 86.07,101.783 85.159,101.783 ; U4.10 88.793,98.183 87.745,99.231 87.745,101.62 ; U4.1 87.782,101.783 ; U5.10 90.388,85.973 90.388,84.199 U5.1 v2(90.838,83.929) ; v1(92.674,77.72) 92.801,77.847 94.214,77.847 C8.1 ; C7.2 94.854,96.369 95.214,96.008 96.182,96.008 96.505,96.33 C17.2 ; R12.1 96.73,96.418 C17.2 ; U6.1 96.412,104.311 C9.1 96.505,103.549 C10.1 C11.1 C12.1 C13.1 ; v2(98.135,98.802) 96.632,98.802 C13.1 ; v1(98.77,94.865) 98.77,96.225 C2.1 97.14,97.151 C14.1 ; 84.038,98.929 84.038,101.783 ; 84.038,101.783 85.159,101.783 ; 85.159,101.783 85.727,101.215 v2(87.34,101.215) 87.745,101.62 ; 87.745,101.62 87.782,101.657 87.782,101.783 ; 87.745,101.62 87.745,101.746 87.782,101.783 ; C17.2 C14.1 ; C14.1 C13.1
PWM0: PWM.1 U4.29 | length 29.6
  Top Layer w0.2: v1(82.641,95.119) 82.768,94.992 85.616,94.992 85.816,94.792 85.816,91.072 86.215,90.674 90.134,90.674 91.404,91.944 95.849,91.944 97.246,90.547 97.246,89.742 98.093,88.896 103.088,88.896 PWM.1
  Bottom Layer w0.2: U4.29 82.641,96.335 v1(82.641,95.119)
PWM1: PWM.2 U4.31 | length 60.9
  Top Layer w0.2: v1(79.847,100.453) 79.593,100.707 79.593,103.12 78.323,103.12 78.323,99.437 78.65,99.11 79.139,99.11 79.339,99.31 79.593,99.31 v1(81.244,97.659)
  Inner1 w0.2: v1(79.847,100.453) 80.228,100.453 81.498,101.723 82.768,101.723 v1(82.768,102.485)
  Inner2 w0.2: v1(82.768,102.485) 84.373,102.485 85.056,103.168 90.261,103.168 90.594,103.501 90.594,104.769 91.406,105.581 98.006,105.581 98.045,105.533 98.054,105.533 101.991,101.596 102.58,101.596 103.796,102.812 104.92,102.812 105.801,101.931 105.801,100.86 106.335,100.326 107.787,100.326 108.168,99.945 108.168,92.452 107.533,91.817 105.247,91.817 PWM.2
  Bottom Layer w0.2: v1(81.244,97.659) 81.444,97.659 81.698,97.405 82.371,97.405 U4.31
PWM2: PWM.3 U4.34 | length 44.5
  Inner2 w0.2: v1(80.609,98.675) 80.355,98.675 79.72,99.31 79.72,101.215 80.482,101.977 84.292,101.977 85.181,102.866 90.388,102.866 90.896,103.374 90.896,104.644 91.531,105.279 97.881,105.279 103.088,100.072 103.85,100.072 104.05,100.272 105.428,100.272 105.755,99.945 105.755,93.311 105.404,92.96 104.104,92.96 PWM.3
  Bottom Layer w0.2: v1(80.609,98.675) 80.701,98.583 81.586,98.583 ; 81.8,98.596 81.586,98.583 ; U4.34 81.586,98.583
SPI0CLK: SPI.4 U4.4 | length 28.8
  Inner1 w0.2: v4(90.86,100.58) 92.166,100.58 92.801,101.215 92.801,101.596 93.182,101.977 93.182,103.628 94.833,105.279 101.056,105.279 101.564,104.771 101.691,104.771 102.221,104.242 v1(102.221,104.136)
  Inner2 w0.2: SPI.4 101.691,94.611 v1(101.691,94.865)
  Bottom Layer w0.2: U4.4 90.857,100.583 v4(90.86,100.58) ; v1(101.691,94.865) 101.564,94.992 101.564,95.881 101.897,96.214 101.897,103.499 102.221,103.823 v1(102.221,104.136)
SPI0CSN: SPI.3 U4.3 | length 32.3
  Inner1 w0.2: v2(92.166,101.596) 92.801,102.231 92.801,103.755 94.706,105.66 101.056,105.66 101.15,105.566 101.531,105.566 v1(102.961,104.136)
  Inner2 w0.2: SPI.3 101.056,91.436 101.056,92.96 102.541,94.445 102.541,95.191 v1(102.191,95.541)
  Bottom Layer w0.2: U4.3 91.15,100.983 91.763,101.596 v2(92.166,101.596) ; v1(102.191,95.541) 102.199,95.549 102.199,103.374 v1(102.961,104.136)
SPI0RX: SPI.2 U4.2 | length 36.2
  Inner1 w0.2: v2(91.785,102.104) 92.42,102.739 92.42,103.882 94.706,106.168 101.931,106.168 v1(103.963,104.136)
  Inner2 w0.2: SPI.2 101.437,89.277 101.437,92.452 102.961,93.976 102.961,96.008 v1(102.834,96.135)
  Bottom Layer w0.2: U4.2 91.064,101.383 v2(91.785,102.104) ; v1(102.834,96.135) 102.707,96.262 102.707,102.88 v1(103.963,104.136)
SPI0TX: SPI.1 U4.5 | length 36.2
  Inner1 w0.2: v1(93.309,101.342) 93.563,101.596 93.563,103.247 95.087,104.771 101.056,104.771 101.564,104.263 v1(101.564,104.136)
  Inner2 w0.2: SPI.1 98.643,86.483 98.643,93.682 v1(101.106,96.144)
  Bottom Layer w0.2: U4.5 91.658,100.183 91.658,100.58 92.039,100.961 92.7,100.961 93.081,101.342 v1(93.309,101.342) ; v1(101.106,96.144) 101.564,96.603 v1(101.564,104.136)
SWCLK0: R16.2 SWD.1 | length 8.3
  Top Layer w0.2: R16.2 SWD.1@80.609,84.933 ; SWD.1@80.609,85.213 SWD.1@80.609,84.933 ; SWD.1@84.361,81.182 SWD.1@80.609,84.933
SWD0: R17.2 R18.1 SWD.3 | length 15.3
  Top Layer w0.2: SWD.3@86.361,81.182 86.361,84.541 85.689,85.213 87.796,85.213 R17.2
  Inner1 w0.2: SWD.3@85.689,85.213 86.07,84.832 v2(86.07,78.101)
  Bottom Layer w0.2: R18.1 85.487,78.863 85.816,78.863 86.07,78.609 v2(86.07,78.101)
U0R: U4.12 UART0.3 UARTS.5 | length 22.7
  Top Layer w0.2: UART0.3 94.561,81.512 96.865,83.816 96.865,88.642 UARTS.5
  Bottom Layer w0.2: U4.12 89.515,97.405 93.69,97.405 94.198,96.897 94.198,94.484 94.706,93.976 94.706,93.341 95.468,92.579 UARTS.5
U0T: U4.11 UART0.1 UARTS.1 | length 21.6
  Top Layer w0.2: UART0.1 92.561,82.052 UARTS.1
  Inner2 w0.2: v1(90.769,97.786) 91.785,97.786 v1(93.436,96.135)
  Bottom Layer w0.2: U4.11 90.766,97.783 v1(90.769,97.786) ; v1(93.436,96.135) 93.436,94.611 94.071,93.976 94.071,86.356 UARTS.1
U1R: U4.28 UART1.3 UARTS.6 | length 32.4
  Top Layer w0.2: UART1.3 v2(102.761,82.653)
  Inner1 w0.2: v1(82.641,90.166) 82.895,90.42 v1(83.53,90.42) ; UARTS.6 94.325,88.642 96.865,88.642 98.262,87.245 98.262,84.417 99.117,83.562 101.852,83.562 v2(102.761,82.653)
  Inner2 w0.2: v1(82.641,90.166) 82.641,93.208 v1(83.458,94.025) ; v1(83.53,90.42) 83.911,90.039 UARTS.6
  Bottom Layer w0.2: U4.28 83.343,94.933 83.458,94.818 v1(83.458,94.025)
U1T: U4.27 UART1.1 UARTS.2 | length 29.1
  Top Layer w0.2: UART1.1 100.761,82.632 v2(100.802,82.673)
  Inner1 w0.2: UARTS.2 95.214,82.673 v2(100.802,82.673)
  Inner2 w0.2: v1(84.165,93.722) 83.022,92.579 83.022,89.023 85.562,86.483 91.404,86.483 UARTS.2
  Bottom Layer w0.2: U4.27 83.743,94.933 83.76,94.916 83.76,94.127 v1(84.165,93.722)
XIN0: C4.2 U4.20 X1.3 | length 7.4
  Bottom Layer w0.2: X1.3 85.605,91.246 ; U4.20 86.543,93.468 85.605,92.53 85.605,91.246 ; C4.2 85.668,91.309 85.605,91.246
XOUT0: R1.2 U4.21 | length 11.1
  Bottom Layer w0.2: R1.2 81.063,88.334 81.498,88.769 83.657,88.769 83.657,89.912 85.181,91.436 85.181,92.833 86.07,93.722 86.07,94.86 86.143,94.933 U4.21
"": pad.TP1 U3.9 U4.24 U4.25 U4.26 U14.1 USB1.4 | length 1.8
  Bottom Layer w0.2: pad.TP1 84.8,94.611 84.943,94.754 U4.24

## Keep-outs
Board Outline Layer:
  lines w0.254 net "": 77.561,77.2 ccw(c78.561,77.2) 78.561,76.2 108.561,76.2 ccw(c108.561,77.2) 109.561,77.2 109.561,107.2 ccw(c108.561,107.2) 108.561,108.2 78.561,108.2 ccw(c78.561,107.2) 77.561,107.2 77.561,77.2

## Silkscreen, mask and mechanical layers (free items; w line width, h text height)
Top Silkscreen Layer:
  text "USB to" at 83.192,91.642 h0.97
  text "I²Cx2,SPIx1, /  UARTx2,SWDx1, /  PWMx3,ADCx3" at 83.388,88.595 h0.86
  text "protocol converter" at 83.436,87.656 h0.85
  text "version 0 build 0" at 83.434,86.894 h0.85
Mechanical Layer:
  circle w0.025 net "": c80.061,105.7 r1.1
  circle w0.025 net "": c80.061,78.7 r1.1
  circle w0.025 net "": c107.061,105.7 r1.1
  circle w0.025 net "": c107.061,78.7 r1.1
